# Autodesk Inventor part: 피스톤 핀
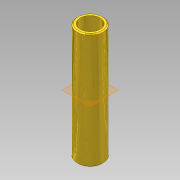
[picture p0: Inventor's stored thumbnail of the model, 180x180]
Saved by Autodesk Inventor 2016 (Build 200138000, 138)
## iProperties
Manager: KYOUNG IL JANG
Company: 한국ATC센터
Created: 2012-10
Part Number: 피스톤 핀
Document SubType Name: Modeling
Density: 1 g/cm^3
Checked By: KYOUNG IL JANG
Vendor: CBT Solutions
Designer: KYOUNG IL JANG
Material: 일반
Appearance: _시험_금속성 금색
Author: KYOUNG IL JANG
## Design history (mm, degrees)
sketch "스케치1"
  geometry: C1 r 6.5 at (0, 0); C2 r 5 at (0, 0); 1 further point
  constraints: 2 centre point, 2 coincident
  dimensions: "d0" = 13 diameter of C1; "d1" = 1.5 radial gap between concentric circles of C1 C2
extrude "돌출1" new body sketch "스케치1" stored distance "d2" = 58; taper "d3" = 0 deg
chamfer "모따기1" distance "d4" = 0.5; stored, may be unused: second distance "d5" = 2, angle "d6" = 45 deg
node "솔리드1"
